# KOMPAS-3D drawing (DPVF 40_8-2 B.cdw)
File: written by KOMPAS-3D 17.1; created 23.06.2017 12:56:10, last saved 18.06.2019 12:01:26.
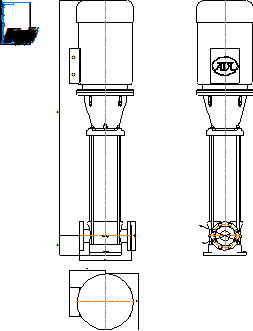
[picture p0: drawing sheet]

Sheet 1: A4, portrait

Title block, sheet 1: name: DPVF 40_8-2 B; material: Внимание! Данный продукт является объектом авторского права ООО «Торговый Дом АДЛ». / Запрещается изменение, копирование, распространение / (в том числе путем копирования на другие сайты и ресурсы в Интернете) / или любое иное использование информации и объектов без предварительного / согласия правообладателя (ООО «Торговый Дом АДЛ»).; scale: 1:1; sheets: 1; organisation: ООО "Торговый дом АДЛ"; sheet format: A4; stored path: C:\Клочков АВ\Насосы\DP PAMS\DPVF 40\Компас 2d\DPVF 40_8-2 B.cdw

Views: Спереди 1
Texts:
  Клочков АВ
  ООО АДЛ ГРУПП
Dimensions and other numbers on the sheet: 365; 250; 400; 209,6; 1663,5; 140; 168,1; 76,2; 1:1; 1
